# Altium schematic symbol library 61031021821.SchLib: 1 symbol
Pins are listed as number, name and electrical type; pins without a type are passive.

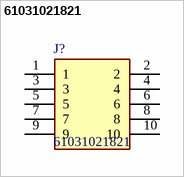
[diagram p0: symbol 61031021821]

## 61031021821
designator J?
Headers & Wire Housings WR-PHD Header 2.54mm SMT; Manufacturer_Name: Wurth Elektronik; Geometry.Height: 7.75mm
footprint 61031021821
pins: 1, 2, 3, 4, 5, 6, 7, 8, 9, 10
